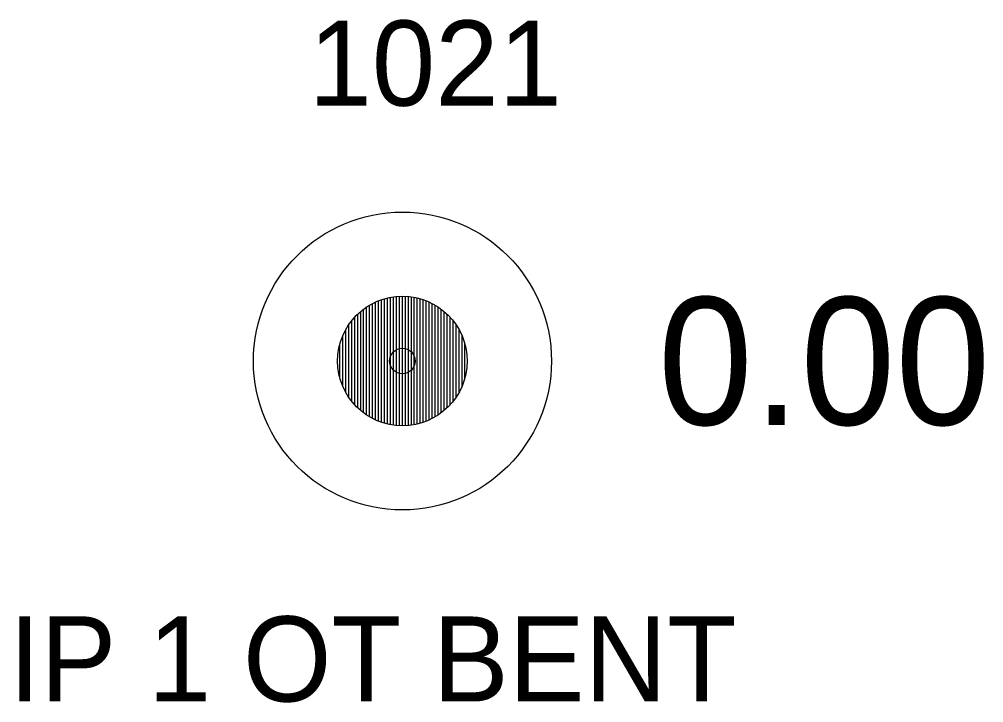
# Model space of a CAD drawing. Extents: x 1664393 to 1667175, y 987029 to 988607.
# Drawn here: x 1664445.07 to 1664456.4, y 988040.91 to 988048.93 of the extents above; entities that cross this region are included whole.
import ezdxf

# ---------------------------------------------------------------- set-up
doc = ezdxf.new("R2010")
doc.units = 0
for name, color, linetype in [('RD_EX_DV_Prop_txCode', 7, 'Continuous'), ('RD_EX_DV_PropPin', 7, 'Continuous'), ('RD_EX_TX_DV_Prop_ELEV', 7, 'Continuous'), ('RD_SMD_Locator', 7, 'Continuous')]:
    doc.layers.add(name, color=color, linetype=linetype)

msp = doc.modelspace()

# ---------------------------------------------------------------- linework, layer by layer
at = {"layer": 'RD_EX_DV_PropPin'}
for p, q in [((1664449.572, 988044.159), (1664449.572, 988045.681)), ((1664449.187, 988044.263), (1664449.187, 988045.576)), ((1664449.222, 988044.244), (1664449.222, 988045.595)), ((1664449.257, 988044.227), (1664449.257, 988045.613)), ((1664449.292, 988044.212), (1664449.292, 988045.627)), ((1664449.327, 988044.199), (1664449.327, 988045.64)), ((1664449.362, 988044.188), (1664449.362, 988045.651)), ((1664449.397, 988044.179), (1664449.397, 988045.66)), ((1664449.432, 988044.172), (1664449.432, 988045.668)), ((1664449.467, 988044.166), (1664449.467, 988045.674)), ((1664449.502, 988044.162), (1664449.502, 988045.678)), ((1664449.537, 988044.16), (1664449.537, 988045.68)), ((1664449.607, 988044.16), (1664449.607, 988045.68)), ((1664449.642, 988044.162), (1664449.642, 988045.678)), ((1664449.677, 988044.166), (1664449.677, 988045.674)), ((1664449.712, 988044.172), (1664449.712, 988045.668)), ((1664449.747, 988044.179), (1664449.747, 988045.66)), ((1664449.782, 988044.188), (1664449.782, 988045.651)), ((1664449.817, 988044.199), (1664449.817, 988045.64)), ((1664449.852, 988044.212), (1664449.852, 988045.627)), ((1664449.887, 988044.227), (1664449.887, 988045.613)), ((1664449.922, 988044.244), (1664449.922, 988045.595)), ((1664449.957, 988044.263), (1664449.957, 988045.576)), ((1664449.047, 988044.369), (1664449.047, 988045.471)), ((1664449.082, 988044.338), (1664449.082, 988045.502)), ((1664449.117, 988044.31), (1664449.117, 988045.53)), ((1664449.152, 988044.285), (1664449.152, 988045.554)), ((1664449.992, 988044.285), (1664449.992, 988045.554)), ((1664450.027, 988044.31), (1664450.027, 988045.53)), ((1664450.062, 988044.338), (1664450.062, 988045.502)), ((1664450.097, 988044.369), (1664450.097, 988045.471)), ((1664448.942, 988044.493), (1664448.942, 988045.346)), ((1664448.977, 988044.446), (1664448.977, 988045.394)), ((1664449.012, 988044.405), (1664449.012, 988045.435)), ((1664450.132, 988044.405), (1664450.132, 988045.435)), ((1664450.167, 988044.446), (1664450.167, 988045.394)), ((1664450.202, 988044.493), (1664450.202, 988045.346)), ((1664448.907, 988044.55), (1664448.907, 988045.289)), ((1664450.237, 988044.55), (1664450.237, 988045.289)), ((1664448.837, 988044.724), (1664448.837, 988045.116)), ((1664448.872, 988044.622), (1664448.872, 988045.218)), ((1664450.272, 988044.622), (1664450.272, 988045.218)), ((1664450.307, 988044.724), (1664450.307, 988045.116))]:
    msp.add_line(p, q, dxfattribs=at)
for radius in [1.75, 0.761]:
    msp.add_circle((1664449.572, 988044.92), radius, dxfattribs=at)
at = {"layer": 'RD_SMD_Locator'}
msp.add_circle((1664449.572, 988044.92), 0.15, dxfattribs=at)

# ---------------------------------------------------------------- texts
at = {"layer": 'RD_EX_DV_Prop_txCode'}
for s, p in [('1021', (1664448.47, 988047.92)), ('IP 1 OT BENT', (1664444.95, 988040.92))]:
    msp.add_text(s, height=1, dxfattribs=at).set_placement(p)
at = {"layer": 'RD_EX_TX_DV_Prop_ELEV'}
msp.add_text('0.00', height=1.5, dxfattribs=at).set_placement((1664452.572, 988044.17))

doc.saveas('drawing.dxf')
